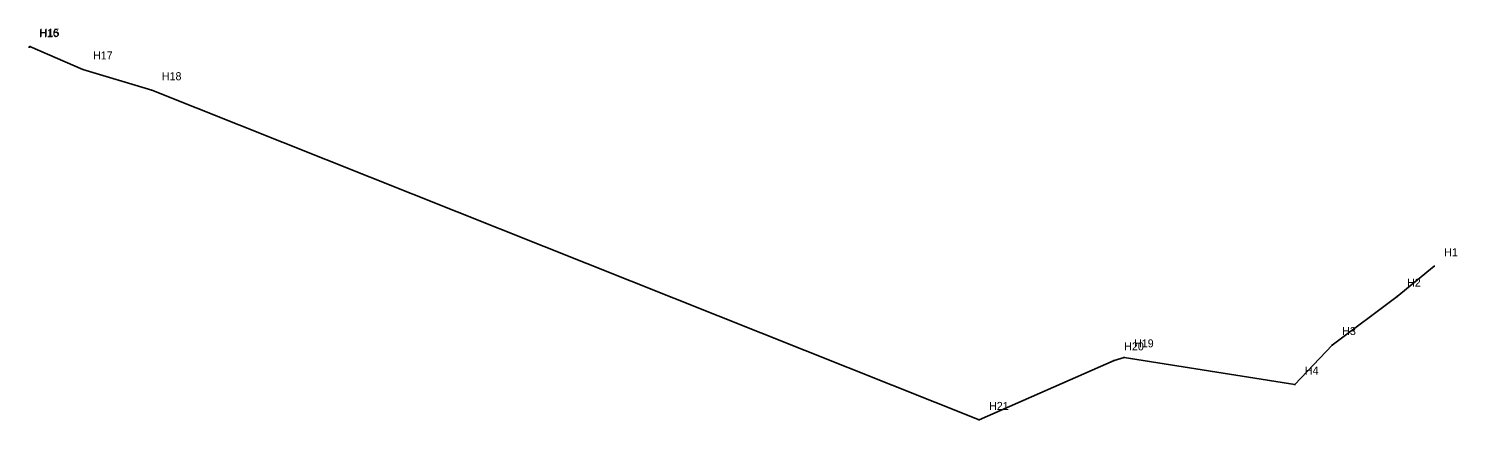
# Model space of a CAD drawing. Extents: x 1727245 to 1729607, y 652704 to 655271.
# Drawn here: x 1728892 to 1729607, y 652704 to 652900 of the extents above; entities that cross this region are included whole.
import ezdxf

# ---------------------------------------------------------------- set-up
doc = ezdxf.new("R2010")
doc.units = 0
for name, color, linetype in [('SURVEY - DRAINAGE - Storm Sewer', 7, 'Continuous'), ('SURVEY - DRAINAGE - Storm Sewer - Points - Locators', 7, 'Continuous'), ('SURVEY - DRAINAGE - Storm Sewer - Points - Numbers', 7, 'Continuous')]:
    doc.layers.add(name, color=color, linetype=linetype)

msp = doc.modelspace()

# ---------------------------------------------------------------- linework, layer by layer
at = {"layer": 'SURVEY - DRAINAGE - Storm Sewer'}
for p, q in [((1728892.65, 652890.86), (1728893.05, 652891.16)), ((1728893.05, 652891.16), (1728919.6, 652879.74)), ((1728919.6, 652879.74), (1728954.02, 652869.34)), ((1728954.02, 652869.34), (1729367.6, 652704.46)), ((1729576.6, 652766.14), (1729595.18, 652781.33)), ((1729544.15, 652741.91), (1729576.6, 652766.14)), ((1729525.5, 652722.17), (1729544.15, 652741.91)), ((1729367.6, 652704.46), (1729435.15, 652734.25)), ((1729435.15, 652734.25), (1729440.09, 652735.75)), ((1729440.09, 652735.75), (1729525.5, 652722.17))]:
    msp.add_line(p, q, dxfattribs=at)
at = {"layer": 'SURVEY - DRAINAGE - Storm Sewer - Points - Locators'}
for p, q in [((1728892.9, 652890.86), (1728892.4, 652890.86)), ((1728892.65, 652890.61), (1728892.65, 652891.11)), ((1728892.65, 652890.86), (1728892.65, 652890.86)), ((1728892.65, 652890.86), (1728892.65, 652890.86)), ((1728893.3, 652891.16), (1728892.8, 652891.16)), ((1728893.05, 652890.91), (1728893.05, 652891.41)), ((1728893.05, 652891.16), (1728893.05, 652891.16)), ((1728893.05, 652891.16), (1728893.05, 652891.16)), ((1728919.85, 652879.74), (1728919.35, 652879.74)), ((1728919.6, 652879.49), (1728919.6, 652879.99)), ((1728919.6, 652879.74), (1728919.6, 652879.74)), ((1728919.6, 652879.74), (1728919.6, 652879.74)), ((1728954.27, 652869.34), (1728953.77, 652869.34)), ((1728954.02, 652869.09), (1728954.02, 652869.59)), ((1728954.02, 652869.34), (1728954.02, 652869.34)), ((1728954.02, 652869.34), (1728954.02, 652869.34)), ((1729595.43, 652781.33), (1729594.93, 652781.33)), ((1729595.18, 652781.08), (1729595.18, 652781.58)), ((1729595.18, 652781.33), (1729595.18, 652781.33)), ((1729595.18, 652781.33), (1729595.18, 652781.33)), ((1729576.85, 652766.14), (1729576.35, 652766.14)), ((1729576.6, 652765.89), (1729576.6, 652766.39)), ((1729576.6, 652766.14), (1729576.6, 652766.14)), ((1729576.6, 652766.14), (1729576.6, 652766.14)), ((1729544.4, 652741.91), (1729543.9, 652741.91)), ((1729544.15, 652741.66), (1729544.15, 652742.16)), ((1729544.15, 652741.91), (1729544.15, 652741.91)), ((1729544.15, 652741.91), (1729544.15, 652741.91)), ((1729435.4, 652734.25), (1729434.9, 652734.25)), ((1729435.15, 652734), (1729435.15, 652734.5)), ((1729435.15, 652734.25), (1729435.15, 652734.25)), ((1729435.15, 652734.25), (1729435.15, 652734.25)), ((1729440.34, 652735.75), (1729439.84, 652735.75)), ((1729440.09, 652735.5), (1729440.09, 652736)), ((1729440.09, 652735.75), (1729440.09, 652735.75)), ((1729440.09, 652735.75), (1729440.09, 652735.75)), ((1729525.75, 652722.17), (1729525.25, 652722.17)), ((1729525.5, 652721.92), (1729525.5, 652722.42)), ((1729525.5, 652722.17), (1729525.5, 652722.17)), ((1729525.5, 652722.17), (1729525.5, 652722.17)), ((1729367.85, 652704.46), (1729367.35, 652704.46)), ((1729367.6, 652704.21), (1729367.6, 652704.71)), ((1729367.6, 652704.46), (1729367.6, 652704.46)), ((1729367.6, 652704.46), (1729367.6, 652704.46))]:
    msp.add_line(p, q, dxfattribs=at)

# ---------------------------------------------------------------- texts
at = {"layer": 'SURVEY - DRAINAGE - Storm Sewer - Points - Numbers'}
for s, p in [('H16', (1728897.65, 652895.86)), ('H15', (1728898.05, 652896.16)), ('H17', (1728924.6, 652884.74)), ('H18', (1728959.02, 652874.34)), ('H1', (1729600.18, 652786.33)), ('H2', (1729581.6, 652771.14)), ('H3', (1729549.15, 652746.91)), ('H20', (1729440.15, 652739.25)), ('H19', (1729445.09, 652740.75)), ('H4', (1729530.5, 652727.17)), ('H21', (1729372.6, 652709.46))]:
    msp.add_text(s, height=4, dxfattribs=at).set_placement(p)

doc.saveas('drawing.dxf')
